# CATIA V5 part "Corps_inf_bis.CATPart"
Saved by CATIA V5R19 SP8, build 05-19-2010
Part number: Corps_inf_bis
Revision: ANY
Definition: UNKNOWN
Nomenclature: 10
Source: Unknown
Bounding box of the stored display mesh (mm): x -45 to 65, y -30.798 to 0, z -202.5 to 0
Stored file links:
  D:\Documents\1_Travail\2- 2I2D\1 - Cours et TD\2- TD\3-TD Assemblage\Pompe AirMan\Corps_inf_bis.CATPart
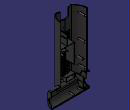
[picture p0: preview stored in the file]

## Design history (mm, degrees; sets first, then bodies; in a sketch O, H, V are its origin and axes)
Body1 "Enlèv. mat.-Extru.16" (main body)
  Solid1: solid without history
